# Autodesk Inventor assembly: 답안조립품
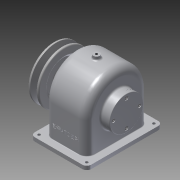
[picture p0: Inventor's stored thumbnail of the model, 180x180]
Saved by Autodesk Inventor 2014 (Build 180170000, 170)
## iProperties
Created: 2016-01
Part Number: 답안조립품
Document SubType Name: Assembly
Designer: user
Author: user
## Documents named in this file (15)
- C:\Users\user\Desktop\460106V1004\답안조립품.iam
- C:\Users\user\Desktop\460106V1004\본체.ipt
- C:\Users\user\Desktop\460106V1004\V-벨트풀리.ipt
- C:\Users\user\Desktop\460106V1004\앞커버.ipt
- C:\Users\user\Desktop\460106V1004\뒤커버.ipt
- C:\Users\user\Desktop\460106V1004\축.ipt
- C:\Users\user\Desktop\460106V1004\베어링 6203.ipt
- C:\Users\user\Desktop\460106V1004\오일씰 28 40 8.ipt
- C:\Users\user\Desktop\460106V1004\부시1.ipt
- C:\Users\user\Desktop\460106V1004\키 - 6 x 6 x 22.ipt
- C:\Users\user\Desktop\460106V1004\스퍼기어.ipt
- C:\Users\user\Desktop\460106V1004\키 - 5 x 5 x 18.ipt
- C:\Users\user\Desktop\460106V1004\멈춤나사 - M4x10.ipt
- C:\Users\user\Desktop\460106V1004\볼트 M3 x 8.ipt
- C:\Users\user\Desktop\460106V1004\볼트 M3 x 10.ipt
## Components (9 placed, 3 different names)
1. V-벨트풀리:1 — Insert:11, Mate:6, Mate:7
2. ISO 4762 M3 x 8:1 — Insert:12
3. ISO 4762 M3 x 8:2
4. ISO 4762 M3 x 8:3
5. ISO 4762 M3 x 8:4
6. ISO 4762 M3 x 10:1 — Insert:13
7. ISO 4762 M3 x 10:2
8. ISO 4762 M3 x 10:3
9. ISO 4762 M3 x 10:4
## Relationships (5: Insert 3, Mate 2)
- Insert:11: V-벨트풀리:1
- Mate:6: V-벨트풀리:1
- Mate:7: V-벨트풀리:1
- Insert:12: ISO 4762 M3 x 8:1
- Insert:13: ISO 4762 M3 x 10:1
